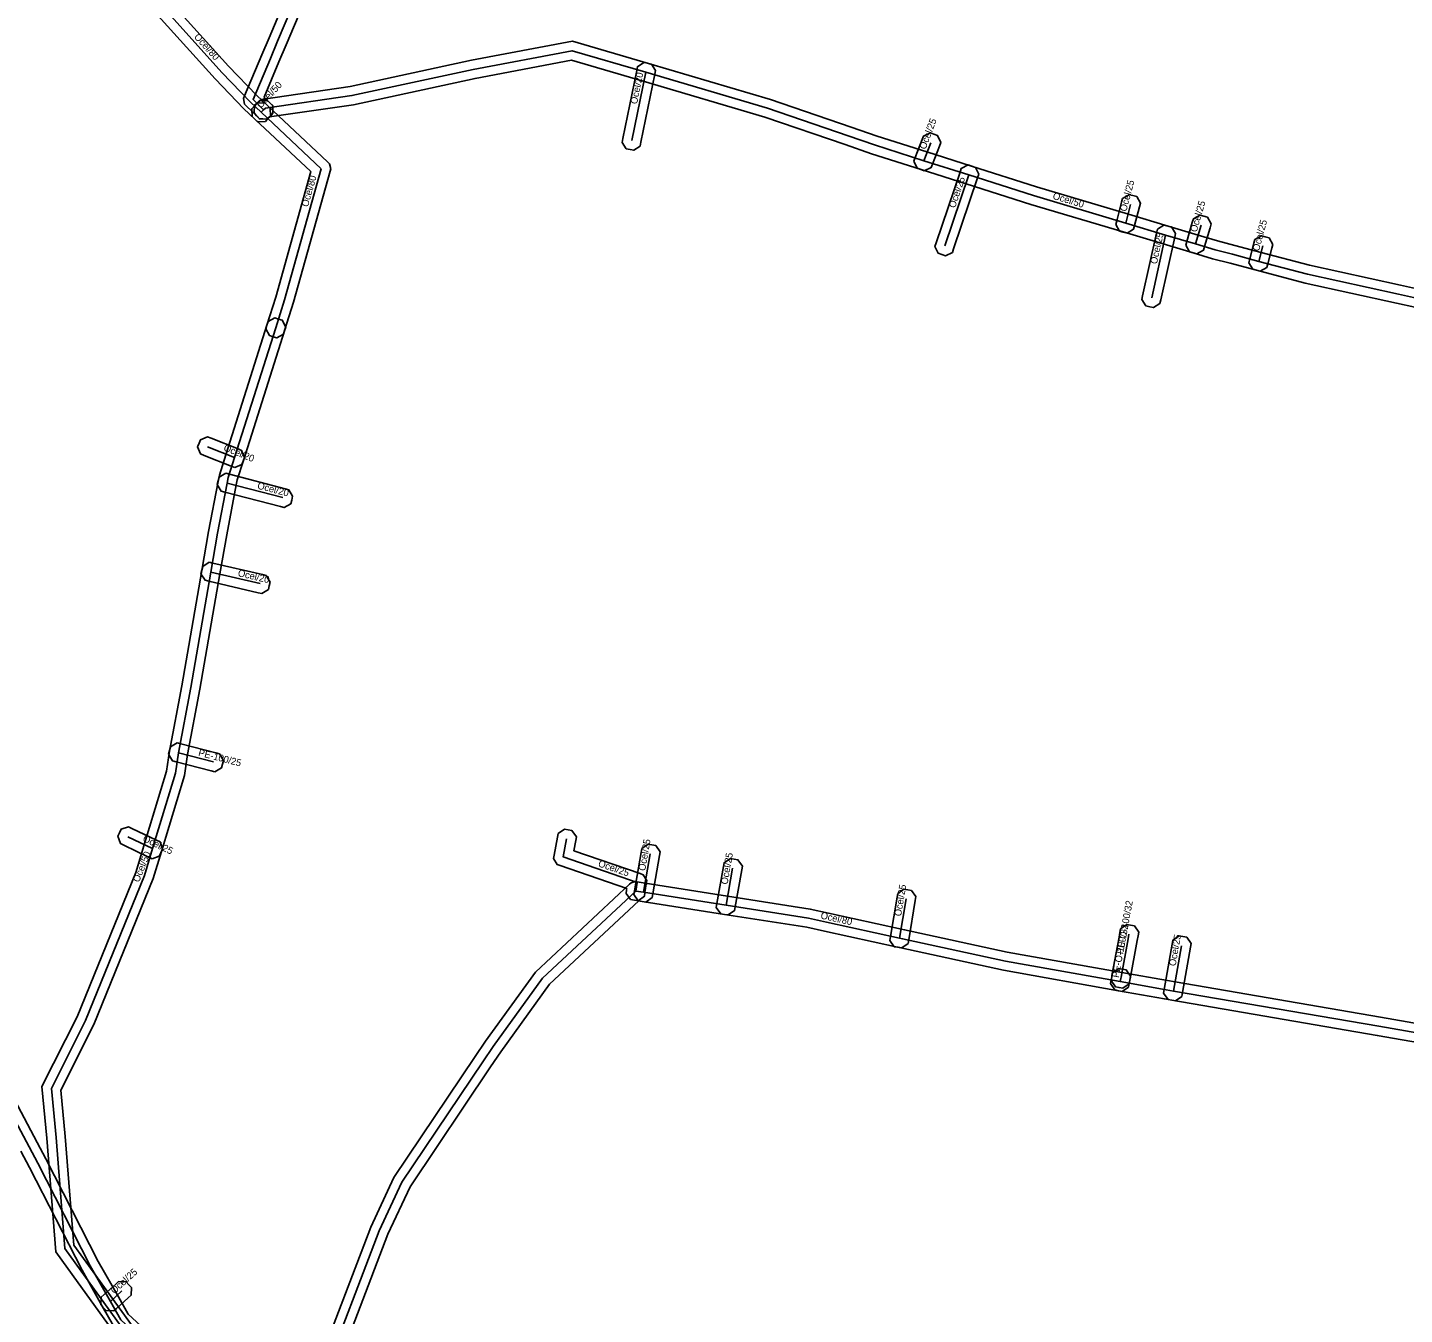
# Model space of a CAD drawing. Extents: x -569373 to -565022, y -1135090 to -1131496.
# Drawn here: x -565447.5 to -565298.7, y -1133985.7 to -1133846.6 of the extents above; entities that cross this region are included whole.
import ezdxf

# ---------------------------------------------------------------- set-up
doc = ezdxf.new("R2010")
doc.units = 0
for name, color, linetype in [('1', 7, 'Continuous'), ('24', 7, 'Continuous'), ('30', 7, 'Continuous')]:
    doc.layers.add(name, color=color, linetype=linetype)

msp = doc.modelspace()

# ---------------------------------------------------------------- linework, layer by layer
at = {"layer": '1'}
for points in [[(-565415.484, -1133838.772), (-565419.598, -1133848.518), (-565420.372, -1133850.359), (-565421.975, -1133854.172), (-565421.329, -1133854.807), (-565421.034, -1133855.097), (-565421.027, -1133855.925), (-565421.317, -1133856.221), (-565421.607, -1133856.516), (-565422.435, -1133856.523), (-565422.731, -1133856.233), (-565423.861, -1133855.123), (-565424.08, -1133854.908), (-565424.201, -1133854.305), (-565424.082, -1133854.022), (-565422.216, -1133849.585), (-565421.442, -1133847.742), (-565417.316, -1133837.968)], [(-565297.631, -1133876.86), (-565299.595, -1133876.43), (-565309.466, -1133874.272), (-565314.748, -1133872.866), (-565317.575, -1133872.107), (-565319.479, -1133871.613), (-565321.596, -1133870.978), (-565324.835, -1133870.018), (-565329.156, -1133868.728), (-565339.115, -1133865.756), (-565346.123, -1133863.523), (-565350.973, -1133861.983), (-565356.344, -1133860.269), (-565359.193, -1133859.291), (-565367.864, -1133856.313), (-565381.012, -1133852.439), (-565388.741, -1133850.167), (-565399.172, -1133852.14), (-565412.302, -1133854.975), (-565421.402, -1133856.299), (-565421.698, -1133856.55), (-565422.524, -1133856.484), (-565422.792, -1133856.168), (-565423.06, -1133855.852), (-565422.994, -1133855.026), (-565422.678, -1133854.758), (-565422.259, -1133854.402), (-565412.658, -1133853.005), (-565399.568, -1133850.18), (-565388.639, -1133848.113), (-565380.448, -1133850.521), (-565367.256, -1133854.407), (-565358.543, -1133857.399), (-565355.716, -1133858.371), (-565350.367, -1133860.077), (-565345.517, -1133861.617), (-565338.525, -1133863.844), (-565328.584, -1133866.812), (-565324.265, -1133868.102), (-565321.024, -1133869.062), (-565318.941, -1133869.687), (-565317.065, -1133870.173), (-565314.232, -1133870.934), (-565308.994, -1133872.328), (-565299.167, -1133874.476), (-565297.229, -1133874.9)], [(-565432.301, -1133995.756), (-565442.07, -1133982.237), (-565444.495, -1133978.9), (-565445.456, -1133966.626), (-565445.983, -1133961.058), (-565442.191, -1133953.516), (-565435.844, -1133937.916), (-565434.977, -1133935.06), (-565432.538, -1133926.988), (-565432.206, -1133924.831), (-565430.874, -1133917.762), (-565428.715, -1133905.309), (-565427.984, -1133901.08), (-565426.941, -1133895.667), (-565426.81, -1133895.011), (-565426.113, -1133892.798), (-565421.663, -1133878.787), (-565421.537, -1133878.392), (-565420.802, -1133878.011), (-565420.407, -1133878.137), (-565420.012, -1133878.263), (-565419.631, -1133878.998), (-565419.757, -1133879.393), (-565424.207, -1133893.402), (-565424.87, -1133895.509), (-565424.979, -1133896.053), (-565426.016, -1133901.44), (-565426.745, -1133905.651), (-565428.906, -1133918.118), (-565430.234, -1133925.169), (-565430.582, -1133927.432), (-565433.063, -1133935.64), (-565433.956, -1133938.584), (-565440.369, -1133954.344), (-565443.937, -1133961.442), (-565443.464, -1133966.454), (-565442.545, -1133978.18), (-565440.45, -1133981.063), (-565430.679, -1133994.584)], [(-565416.655, -1133992.539), (-565410.452, -1133976.23), (-565407.953, -1133970.886), (-565399.174, -1133957.82), (-565398.05, -1133956.148), (-565392.643, -1133948.675), (-565382.492, -1133939.199), (-565382.324, -1133939.042), (-565381.886, -1133938.906), (-565381.659, -1133938.941), (-565380.807, -1133939.072), (-565371.895, -1133940.472), (-565362.955, -1133941.877), (-565360.975, -1133942.313), (-565353.089, -1133944.042), (-565352.76, -1133944.112), (-565341.676, -1133946.519), (-565329.286, -1133948.724), (-565324.336, -1133949.605), (-565323.539, -1133949.745), (-565301.349, -1133953.555), (-565278.708, -1133957.505)], [(-565279.052, -1133959.475), (-565301.691, -1133955.525), (-565323.881, -1133951.715), (-565324.684, -1133951.575), (-565329.636, -1133950.694), (-565342.064, -1133948.481), (-565353.18, -1133946.068), (-565353.511, -1133945.998), (-565361.405, -1133944.267), (-565363.325, -1133943.843), (-565372.205, -1133942.448), (-565381.113, -1133941.048), (-565381.482, -1133940.992), (-565391.137, -1133950.005), (-565396.41, -1133957.292), (-565397.514, -1133958.936), (-565406.207, -1133971.874), (-565408.608, -1133977.01), (-565414.865, -1133993.461)], [(-565451.406, -1133957.886), (-565446.488, -1133967.089), (-565445.543, -1133968.857), (-565439.889, -1133979.946), (-565437.72, -1133983.778), (-565436.667, -1133985.641), (-565428.811, -1133992.877)], [(-565438.253, -1133986.899), (-565439.46, -1133984.762), (-565441.651, -1133980.894), (-565447.317, -1133969.783), (-565448.252, -1133968.031)]]:
    msp.add_lwpolyline(points, dxfattribs=at)
for points in [[(-565436.756, -1133838.768), (-565436.475, -1133839.072), (-565432.99, -1133842.847), (-565431.606, -1133844.391), (-565425.809, -1133850.818), (-565422.746, -1133853.99), (-565421.602, -1133855.074), (-565421.301, -1133855.359), (-565421.279, -1133856.187), (-565421.564, -1133856.488), (-565421.849, -1133856.789), (-565422.677, -1133856.811), (-565422.978, -1133856.526), (-565424.154, -1133855.41), (-565427.271, -1133852.182), (-565433.094, -1133845.729), (-565434.47, -1133844.193), (-565437.945, -1133840.428), (-565438.226, -1133840.124), (-565438.192, -1133839.296), (-565437.888, -1133839.015), (-565437.584, -1133838.734)], [(-565379.667, -1133851.274), (-565379.75, -1133851.68), (-565381.25, -1133859.04), (-565381.333, -1133859.446), (-565382.024, -1133859.903), (-565382.43, -1133859.82), (-565382.836, -1133859.737), (-565383.293, -1133859.046), (-565383.21, -1133858.64), (-565381.71, -1133851.28), (-565381.627, -1133850.874), (-565380.936, -1133850.417), (-565380.53, -1133850.5), (-565380.124, -1133850.583)], [(-565423.305, -1133855.423), (-565423.023, -1133855.12), (-565422.763, -1133854.84), (-565422.481, -1133854.536), (-565421.653, -1133854.505), (-565421.35, -1133854.787), (-565421.046, -1133855.069), (-565421.015, -1133855.897), (-565421.297, -1133856.2), (-565421.557, -1133856.48), (-565421.839, -1133856.784), (-565422.667, -1133856.815), (-565422.97, -1133856.533), (-565423.274, -1133856.251)], [(-565421.907, -1133854.787), (-565421.605, -1133855.071), (-565415.125, -1133861.161), (-565414.922, -1133861.352), (-565414.772, -1133861.89), (-565414.847, -1133862.159), (-565418.801, -1133876.323), (-565419.755, -1133879.387), (-565419.878, -1133879.783), (-565420.612, -1133880.168), (-565421.007, -1133880.045), (-565421.403, -1133879.922), (-565421.788, -1133879.188), (-565421.665, -1133878.793), (-565420.719, -1133875.757), (-565416.936, -1133862.204), (-565422.975, -1133856.529), (-565423.277, -1133856.245), (-565423.303, -1133855.417), (-565423.019, -1133855.115), (-565422.735, -1133854.813)], [(-565351.752, -1133861.064), (-565351.605, -1133860.676), (-565350.875, -1133858.746), (-565350.729, -1133858.359), (-565349.974, -1133858.018), (-565349.586, -1133858.165), (-565349.199, -1133858.311), (-565348.858, -1133859.066), (-565349.005, -1133859.454), (-565349.735, -1133861.384), (-565349.881, -1133861.771), (-565350.636, -1133862.112), (-565351.024, -1133861.965), (-565351.411, -1133861.819)], [(-565344.74, -1133862.498), (-565344.873, -1133862.891), (-565347.463, -1133870.541), (-565347.596, -1133870.933), (-565348.338, -1133871.3), (-565348.731, -1133871.167), (-565349.123, -1133871.034), (-565349.49, -1133870.292), (-565349.357, -1133869.899), (-565346.767, -1133862.249), (-565346.634, -1133861.857), (-565345.892, -1133861.49), (-565345.499, -1133861.623), (-565345.107, -1133861.756)], [(-565329.943, -1133867.914), (-565329.837, -1133867.514), (-565329.307, -1133865.514), (-565329.201, -1133865.113), (-565328.484, -1133864.697), (-565328.084, -1133864.803), (-565327.683, -1133864.909), (-565327.267, -1133865.626), (-565327.373, -1133866.026), (-565327.903, -1133868.026), (-565328.009, -1133868.427), (-565328.726, -1133868.843), (-565329.126, -1133868.737), (-565329.527, -1133868.631)], [(-565323.484, -1133868.874), (-565323.574, -1133869.278), (-565325.084, -1133876.048), (-565325.174, -1133876.452), (-565325.874, -1133876.896), (-565326.278, -1133876.806), (-565326.682, -1133876.716), (-565327.126, -1133876.016), (-565327.036, -1133875.612), (-565325.526, -1133868.842), (-565325.436, -1133868.438), (-565324.736, -1133867.994), (-565324.332, -1133868.084), (-565323.928, -1133868.174)], [(-565322.386, -1133870.135), (-565322.269, -1133869.738), (-565321.669, -1133867.698), (-565321.552, -1133867.3), (-565320.825, -1133866.904), (-565320.428, -1133867.021), (-565320.03, -1133867.138), (-565319.634, -1133867.865), (-565319.751, -1133868.262), (-565320.351, -1133870.302), (-565320.468, -1133870.7), (-565321.195, -1133871.096), (-565321.592, -1133870.979), (-565321.99, -1133870.862)], [(-565315.563, -1133872.043), (-565315.456, -1133871.643), (-565315.006, -1133869.953), (-565314.9, -1133869.552), (-565314.183, -1133869.137), (-565313.783, -1133869.244), (-565313.382, -1133869.35), (-565312.967, -1133870.067), (-565313.074, -1133870.467), (-565313.524, -1133872.157), (-565313.63, -1133872.558), (-565314.347, -1133872.973), (-565314.747, -1133872.866), (-565315.148, -1133872.76)], [(-565425.148, -1133894.182), (-565425.532, -1133894.028), (-565428.452, -1133892.858), (-565428.836, -1133892.704), (-565429.162, -1133891.942), (-565429.008, -1133891.558), (-565428.854, -1133891.174), (-565428.092, -1133890.848), (-565427.708, -1133891.002), (-565424.788, -1133892.172), (-565424.404, -1133892.326), (-565424.078, -1133893.088), (-565424.232, -1133893.472), (-565424.386, -1133893.856)], [(-565426.108, -1133894.788), (-565425.707, -1133894.893), (-565419.707, -1133896.463), (-565419.306, -1133896.568), (-565418.888, -1133897.282), (-565418.993, -1133897.683), (-565419.098, -1133898.084), (-565419.812, -1133898.502), (-565420.213, -1133898.397), (-565426.213, -1133896.827), (-565426.614, -1133896.722), (-565427.032, -1133896.008), (-565426.927, -1133895.607), (-565426.822, -1133895.206)], [(-565427.907, -1133904.412), (-565427.504, -1133904.506), (-565422.164, -1133905.746), (-565421.761, -1133905.84), (-565421.322, -1133906.543), (-565421.416, -1133906.946), (-565421.51, -1133907.349), (-565422.213, -1133907.788), (-565422.616, -1133907.694), (-565427.956, -1133906.454), (-565428.359, -1133906.36), (-565428.798, -1133905.657), (-565428.704, -1133905.254), (-565428.61, -1133904.851)], [(-565427.301, -1133927.052), (-565427.702, -1133926.948), (-565431.472, -1133925.968), (-565431.873, -1133925.864), (-565432.292, -1133925.149), (-565432.188, -1133924.748), (-565432.084, -1133924.347), (-565431.369, -1133923.928), (-565430.968, -1133924.032), (-565427.198, -1133925.012), (-565426.797, -1133925.116), (-565426.378, -1133925.831), (-565426.482, -1133926.232), (-565426.586, -1133926.633)], [(-565434.081, -1133936.431), (-565434.454, -1133936.251), (-565437.134, -1133934.961), (-565437.507, -1133934.781), (-565437.781, -1133933.999), (-565437.601, -1133933.626), (-565437.421, -1133933.253), (-565436.639, -1133932.979), (-565436.266, -1133933.159), (-565433.586, -1133934.449), (-565433.213, -1133934.629), (-565432.939, -1133935.411), (-565433.119, -1133935.784), (-565433.299, -1133936.157)], [(-565388.232, -1133934.07), (-565388.306, -1133934.478), (-565388.504, -1133935.574), (-565381.344, -1133938.045), (-565381.003, -1133938.163), (-565380.628, -1133938.78), (-565380.681, -1133939.137), (-565380.821, -1133940.077), (-565380.882, -1133940.487), (-565381.547, -1133940.98), (-565381.957, -1133940.919), (-565382.367, -1133940.858), (-565382.86, -1133940.193), (-565382.799, -1133939.783), (-565382.781, -1133939.664), (-565389.966, -1133937.185), (-565390.316, -1133937.065), (-565390.69, -1133936.426), (-565390.624, -1133936.062), (-565390.274, -1133934.122), (-565390.201, -1133933.714), (-565389.52, -1133933.242), (-565389.112, -1133933.316), (-565388.704, -1133933.389)], [(-565382.016, -1133940.297), (-565381.945, -1133939.889), (-565381.225, -1133935.749), (-565381.154, -1133935.341), (-565380.477, -1133934.864), (-565380.069, -1133934.935), (-565379.661, -1133935.006), (-565379.184, -1133935.683), (-565379.255, -1133936.091), (-565379.975, -1133940.231), (-565380.046, -1133940.639), (-565380.723, -1133941.116), (-565381.131, -1133941.045), (-565381.539, -1133940.974)], [(-565373.106, -1133941.696), (-565373.035, -1133941.288), (-565372.335, -1133937.288), (-565372.264, -1133936.88), (-565371.586, -1133936.404), (-565371.178, -1133936.475), (-565370.77, -1133936.546), (-565370.294, -1133937.224), (-565370.365, -1133937.632), (-565371.065, -1133941.632), (-565371.136, -1133942.04), (-565371.814, -1133942.516), (-565372.222, -1133942.445), (-565372.63, -1133942.374)], [(-565354.354, -1133945.264), (-565354.286, -1133944.855), (-565353.576, -1133940.605), (-565353.508, -1133940.197), (-565352.834, -1133939.716), (-565352.425, -1133939.784), (-565352.017, -1133939.852), (-565351.536, -1133940.526), (-565351.604, -1133940.935), (-565352.314, -1133945.185), (-565352.382, -1133945.593), (-565353.056, -1133946.074), (-565353.465, -1133946.006), (-565353.873, -1133945.938)], [(-565330.456, -1133949.592), (-565330.381, -1133949.184), (-565330.353, -1133949.037), (-565329.589, -1133944.906), (-565329.499, -1133944.421), (-565329.424, -1133944.013), (-565328.741, -1133943.544), (-565328.334, -1133943.62), (-565327.926, -1133943.695), (-565327.457, -1133944.378), (-565327.533, -1133944.785), (-565327.623, -1133945.27), (-565328.387, -1133949.399), (-565328.413, -1133949.546), (-565328.488, -1133949.953), (-565329.17, -1133950.424), (-565329.578, -1133950.349), (-565329.985, -1133950.274)], [(-565324.767, -1133950.965), (-565324.695, -1133950.557), (-565323.835, -1133945.657), (-565323.763, -1133945.249), (-565323.085, -1133944.773), (-565322.677, -1133944.845), (-565322.269, -1133944.917), (-565321.793, -1133945.595), (-565321.865, -1133946.003), (-565322.725, -1133950.903), (-565322.797, -1133951.311), (-565323.475, -1133951.787), (-565323.883, -1133951.715), (-565324.291, -1133951.643)], [(-565330.52, -1133949.933), (-565330.444, -1133949.526), (-565330.38, -1133949.182), (-565330.304, -1133948.775), (-565329.621, -1133948.306), (-565329.214, -1133948.382), (-565328.807, -1133948.458), (-565328.338, -1133949.141), (-565328.414, -1133949.548), (-565328.478, -1133949.892), (-565328.554, -1133950.299), (-565329.237, -1133950.768), (-565329.644, -1133950.692), (-565330.051, -1133950.616)], [(-565439.568, -1133983.806), (-565439.261, -1133983.528), (-565438.001, -1133982.388), (-565437.694, -1133982.11), (-565436.866, -1133982.152), (-565436.588, -1133982.459), (-565436.31, -1133982.766), (-565436.352, -1133983.594), (-565436.659, -1133983.872), (-565437.919, -1133985.012), (-565438.226, -1133985.29), (-565439.054, -1133985.248), (-565439.332, -1133984.941), (-565439.61, -1133984.634)]]:
    msp.add_lwpolyline(points, close=True, dxfattribs=at)
at = {"layer": '24'}
for points in [[(-565422.03, -1133855.52), (-565423.16, -1133854.41), (-565421.294, -1133849.972), (-565420.52, -1133848.13), (-565416.4, -1133838.37), (-565415.57, -1133836.55), (-565414.17, -1133833.49), (-565413.34, -1133831.67), (-565413.21, -1133831.4), (-565407.71, -1133820.04), (-565406.84, -1133818.24), (-565406.71, -1133817.97)], [(-565437.21, -1133839.75), (-565433.73, -1133843.52), (-565432.35, -1133845.06), (-565426.54, -1133851.5), (-565423.45, -1133854.7), (-565422.29, -1133855.8)], [(-565422.03, -1133855.52), (-565421.83, -1133855.35), (-565412.48, -1133853.99), (-565399.37, -1133851.16), (-565388.69, -1133849.14), (-565380.73, -1133851.48), (-565367.56, -1133855.36), (-565358.868, -1133858.345), (-565356.03, -1133859.32), (-565350.67, -1133861.03), (-565345.82, -1133862.57), (-565338.82, -1133864.8), (-565328.87, -1133867.77), (-565324.55, -1133869.06), (-565321.31, -1133870.02), (-565319.21, -1133870.65), (-565317.32, -1133871.14), (-565314.49, -1133871.9), (-565309.23, -1133873.3), (-565299.381, -1133875.453), (-565297.43, -1133875.88)], [(-565380.73, -1133851.48), (-565382.23, -1133858.84)], [(-565422.29, -1133855.8), (-565422.03, -1133855.52)], [(-565422.29, -1133855.8), (-565415.81, -1133861.89), (-565419.76, -1133876.04), (-565420.71, -1133879.09)], [(-565350.67, -1133861.03), (-565349.94, -1133859.1)], [(-565345.82, -1133862.57), (-565348.41, -1133870.22)], [(-565328.87, -1133867.77), (-565328.34, -1133865.77)], [(-565321.31, -1133870.02), (-565320.71, -1133867.98)], [(-565324.55, -1133869.06), (-565326.06, -1133875.83)], [(-565314.49, -1133871.9), (-565314.04, -1133870.21)], [(-565420.71, -1133879.09), (-565425.16, -1133893.1), (-565425.84, -1133895.26), (-565425.96, -1133895.86), (-565427, -1133901.26), (-565427.73, -1133905.48), (-565429.89, -1133917.94), (-565431.22, -1133925), (-565431.56, -1133927.21), (-565434.02, -1133935.35), (-565434.9, -1133938.25), (-565441.28, -1133953.93), (-565444.96, -1133961.25), (-565444.46, -1133966.54), (-565443.52, -1133978.54), (-565441.26, -1133981.65), (-565431.49, -1133995.17)], [(-565425.16, -1133893.1), (-565428.08, -1133891.93)], [(-565425.96, -1133895.86), (-565419.96, -1133897.43)], [(-565427.73, -1133905.48), (-565422.39, -1133906.72)], [(-565427.45, -1133925.98), (-565431.22, -1133925)], [(-565420.63, -1134001.3), (-565421.33, -1134000.81), (-565421.78, -1134000.41), (-565427.03, -1133995.78), (-565429.48, -1133993.62), (-565437.46, -1133986.27), (-565438.59, -1133984.27), (-565440.77, -1133980.42), (-565446.43, -1133969.32), (-565447.37, -1133967.56), (-565452.18, -1133958.56), (-565456.45, -1133955.46), (-565458.091, -1133954.322), (-565459.958, -1133953.028), (-565461.6, -1133951.89), (-565466.84, -1133948.57), (-565468.53, -1133947.5), (-565477.83, -1133941.92), (-565491.31, -1133933.86), (-565493.715, -1133932.311), (-565498.14, -1133929.46)], [(-565434.02, -1133935.35), (-565436.7, -1133934.06)], [(-565389.29, -1133934.3), (-565389.64, -1133936.24), (-565381.67, -1133938.99), (-565381.81, -1133939.93)], [(-565380.96, -1133940.06), (-565380.24, -1133935.92)], [(-565372.05, -1133941.46), (-565371.35, -1133937.46)], [(-565278.88, -1133958.49), (-565301.52, -1133954.54), (-565323.71, -1133950.73), (-565324.51, -1133950.59), (-565329.461, -1133949.709), (-565341.87, -1133947.5), (-565352.97, -1133945.09), (-565353.3, -1133945.02), (-565361.19, -1133943.29), (-565363.14, -1133942.86), (-565372.05, -1133941.46), (-565380.96, -1133940.06), (-565381.81, -1133939.93), (-565391.89, -1133949.34), (-565397.23, -1133956.72), (-565398.344, -1133958.378), (-565407.08, -1133971.38), (-565409.53, -1133976.62), (-565415.76, -1133993), (-565416.14, -1133993.57)], [(-565353.3, -1133945.02), (-565352.59, -1133940.77)], [(-565329.397, -1133949.365), (-565329.37, -1133949.218), (-565328.606, -1133945.088), (-565328.516, -1133944.603)], [(-565323.71, -1133950.73), (-565322.85, -1133945.83)], [(-565329.461, -1133949.709), (-565329.397, -1133949.365)], [(-565438.59, -1133984.27), (-565437.33, -1133983.13)]]:
    msp.add_lwpolyline(points, dxfattribs=at)

# ---------------------------------------------------------------- texts
at = {"layer": '30'}
for s, rotation, p in [('Ocel/80', 312.05595, (-565429.597, -1133847.69)), ('Ocel/20', 78.48063, (-565381.68, -1133854.96)), ('Ocel/50', 47.1211, (-565422.326, -1133855.423)), ('Ocel/25', 69.28146, (-565350.505, -1133859.865)), ('Ocel/80', 74.40282, (-565417.232, -1133866.069)), ('Ocel/25', 71.29585, (-565347.315, -1133866.195)), ('Ocel/25', 75.15777, (-565328.805, -1133866.57)), ('Ocel/50', 343.38003, (-565336.812, -1133865.14)), ('Ocel/25', 73.61046, (-565321.21, -1133868.8)), ('Ocel/25', 75.08969, (-565314.465, -1133870.855)), ('Ocel/25', 77.42639, (-565325.505, -1133872.245)), ('Ocel/20', 338.16477, (-565426.42, -1133892.315)), ('Ocel/20', 345.33637, (-565422.76, -1133896.445)), ('Ocel/20', 346.92705, (-565424.86, -1133905.9)), ('PE-100/25', 345.42863, (-565429.135, -1133925.29)), ('Ocel/25', 334.29647, (-565435.16, -1133934.505)), ('Ocel/25', 80.13419, (-565380.8, -1133937.79)), ('Ocel/50', 67.85919, (-565435.503, -1133939.04)), ('Ocel/25', 340.96332, (-565385.938, -1133937.248)), ('Ocel/25', 80.07375, (-565371.9, -1133939.26)), ('Ocel/25', 80.51582, (-565353.145, -1133942.695)), ('PE-O-100/32', 79.51945, (-565329.157, -1133946.784)), ('Ocel/80', 347.56456, (-565361.886, -1133942.892)), ('PE-O-100/32', 79.46082, (-565329.629, -1133949.337)), ('Ocel/25', 80.04539, (-565323.48, -1133948.08)), ('Ocel/25', 42.13759, (-565438.16, -1133983.5))]:
    msp.add_text(s, height=0.75, rotation=rotation, dxfattribs=at).set_placement(p)

doc.saveas('drawing.dxf')
